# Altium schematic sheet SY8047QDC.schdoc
size 127 x 101 mm
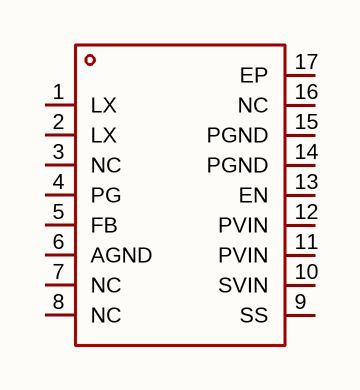
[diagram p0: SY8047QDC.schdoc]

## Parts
U?  sy8047qdc  [TQFN-16_L3.0-W3.0-P0.50-TL-EP1.6]  (value not drawn)

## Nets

Not connected (* = marked no-connect by the designer): U? 1(LX) 2(LX) 3(NC) 4(PG) 5(FB) 6(AGND) 7(NC) 8(NC) 9(SS) 10(SVIN) 11(PVIN) 12(PVIN) 13(EN) 14(PGND) 15(PGND) 16(NC) 17(EP)

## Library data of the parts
U? = sy8047qdc: 功能类型:降压型;工作电压:2.5V~5.5V;输出电压:-;输出电流:4A;输出类型:可调;; Manufacturer: Silergy(矽力杰); AddInBom: yes; ModelId: 3f7615f5bc1745938c263a2bc8ac133f; ModelTransform: 118.8974,118.8974,0,0,0,0,-0.003,-0.002,0; Function: 降压型; Output Current: 4A; Frequency - Switching: 1.25MHz; Synchronous Rectifier: 是; Number of Outputs: 1; Topology: 降压式; Quiescent Current: 18uA; Switch tube (built-in/external): 内置; Output Type: 可调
